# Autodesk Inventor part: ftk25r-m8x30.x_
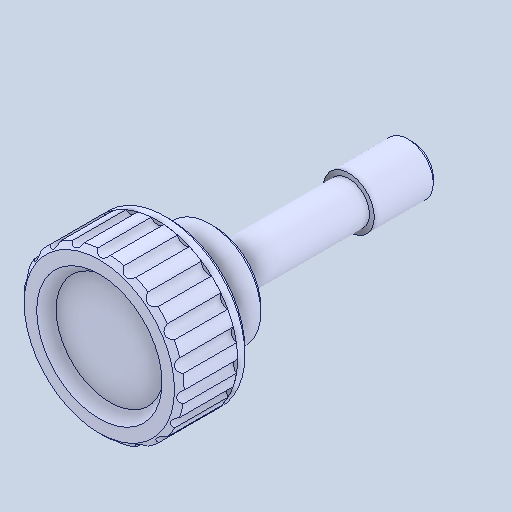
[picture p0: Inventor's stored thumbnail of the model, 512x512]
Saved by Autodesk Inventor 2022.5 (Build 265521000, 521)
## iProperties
Created: 2024-06
Part Number: ftk25r-m8x30.x_
Material: 一般
Document SubType Name: Modeling
Designer: ImaoCorp
Density: 1 g/cm^3
Appearance: 既定
Author: ImaoCorp
Sending System: SOLIDWORKS 2022-2022290
MC: AMD64
MC_MODEL: Intel64 Family 6 Model 60 Stepping 3, GenuineIntel
OS: Windows_NT
FRU: Parasolid Version 33.1, build 260,  4-25-2022
FORMAT: text
GUISE: transmit
KEY: FILEftk25r-m8x30.x_t
DATE: Fri Jun 28 15:20:13 2024
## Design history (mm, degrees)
feature "Base1"
node "ソリッド1"
